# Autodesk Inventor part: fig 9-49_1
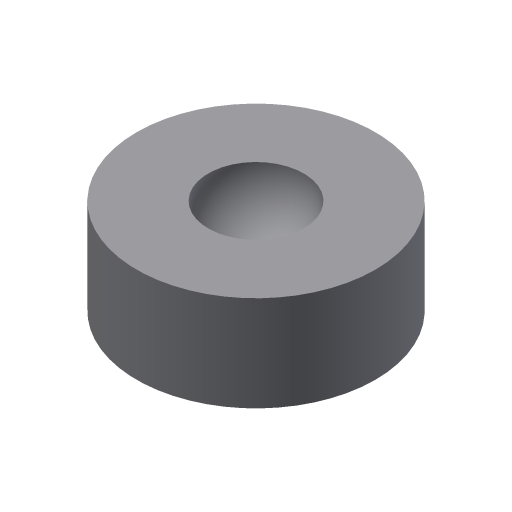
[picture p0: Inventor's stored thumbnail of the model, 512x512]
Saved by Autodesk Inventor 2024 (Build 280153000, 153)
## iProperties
Created: 2013-03
Part Number: fig 9-49_1
Material: Generic
Document SubType Name: Modeling
Designer: CADCIM
Density: 1 g/cm^3
Appearance: Default
Author: CADCIM
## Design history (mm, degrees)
sketch "Sketch1"
  geometry: C1 r 12.5 at (0, 0); 1 further point
  constraints: 1 centre point, 1 coincident
  dimensions: "d0" = 25 diameter of C1
extrude "Extrusion1" new body sketch "Sketch1" distance "d2" = 10; taper "d3" = 0 deg
revolve "Revolution1" stored, may be unused: angle "d6" = 90 deg
body "Solid1"
sketch "Sketch2"
  geometry: L1 (12.5, 10)-(-12.5, 10) reference; L2 (-5, 10)-(5, 10); A1 r 5 centre (0, 10) between (-5, 10) and (5, 10); 1 further point
  constraints: 2 end point, 2 point on circle, 2 point on line, 1 centre point, 1 midpoint
  dimensions: "d4" = 10 diameter of A1
